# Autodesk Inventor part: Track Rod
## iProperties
Shininess: 100.0
Angle Display Precision: 2
Document Length Units: 11269
Document Angle Units: 11279
Document Time Units: 11290
Document Mass Units: 11283
Document Length Units Precision: 3
Document Angle Units Precision: 2
Compacted: True
Created: 2001-08
Part Number: Track Rod
Document SubType Name: Modeling
Designer: Martin Budgell
Density: 0.0
Volumn: 0.0
Area: 0.0
PropertySet Name: Model Information
Control State: 0
Master: False
Checked Out: False
Author: Martin Budgell
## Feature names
1. Extrusion1
2. Chamfer1
